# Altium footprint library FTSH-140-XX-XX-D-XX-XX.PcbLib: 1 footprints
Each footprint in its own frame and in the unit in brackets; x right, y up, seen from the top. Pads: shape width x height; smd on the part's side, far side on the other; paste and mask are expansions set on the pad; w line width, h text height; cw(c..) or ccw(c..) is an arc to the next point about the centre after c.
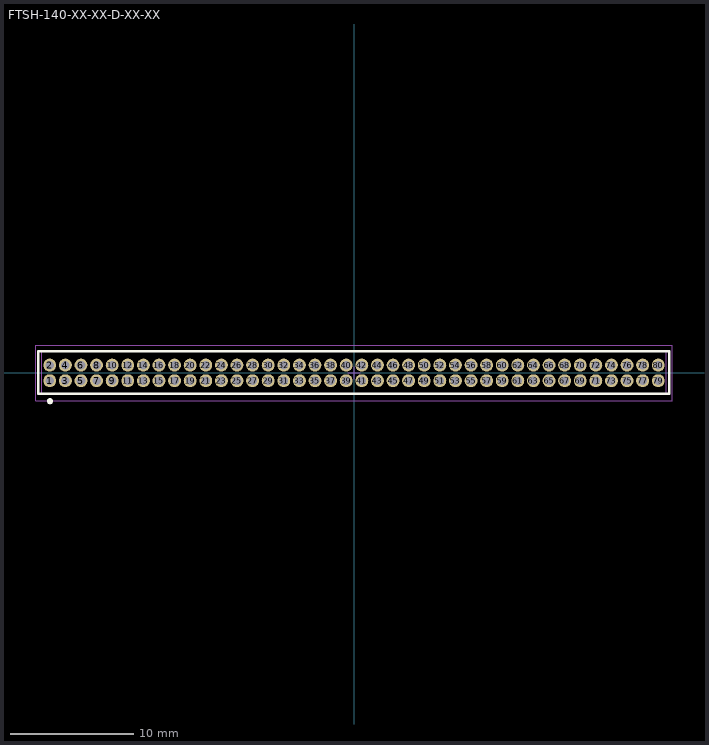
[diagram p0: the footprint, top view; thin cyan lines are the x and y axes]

## FTSH-140-XX-XX-D-XX-XX [mm] "1.27mm pitch, 80 pin, terminal strip; PTH"
height 3.05
pads (80):
  round 1.05 hole 0.7 unplated mask+0: 1(-24.765,-0.635) 2(-24.765,0.635) 3(-23.495,-0.635) 4(-23.495,0.635) 5(-22.225,-0.635) 6(-22.225,0.635) 7(-20.955,-0.635) 8(-20.955,0.635) 9(-19.685,-0.635) 10(-19.685,0.635) 11(-18.415,-0.635) 12(-18.415,0.635) 13(-17.145,-0.635) 14(-17.145,0.635) 15(-15.875,-0.635) 16(-15.875,0.635) 17(-14.605,-0.635) 18(-14.605,0.635) 19(-13.335,-0.635) 20(-13.335,0.635) 21(-12.065,-0.635) 22(-12.065,0.635) 23(-10.795,-0.635) 24(-10.795,0.635) 25(-9.525,-0.635) 26(-9.525,0.635) 27(-8.255,-0.635) 28(-8.255,0.635) 29(-6.985,-0.635) 30(-6.985,0.635) 31(-5.715,-0.635) 32(-5.715,0.635) 33(-4.445,-0.635) 34(-4.445,0.635) 35(-3.175,-0.635) 36(-3.175,0.635) 37(-1.905,-0.635) 38(-1.905,0.635) 39(-0.635,-0.635) 40(-0.635,0.635) 41(0.635,-0.635) 42(0.635,0.635) 43(1.905,-0.635) 44(1.905,0.635) 45(3.175,-0.635) 46(3.175,0.635) 47(4.445,-0.635) 48(4.445,0.635) 49(5.715,-0.635) 50(5.715,0.635) 51(6.985,-0.635) 52(6.985,0.635) 53(8.255,-0.635) 54(8.255,0.635) 55(9.525,-0.635) 56(9.525,0.635) 57(10.795,-0.635) 58(10.795,0.635) 59(12.065,-0.635) 60(12.065,0.635) 61(13.335,-0.635) 62(13.335,0.635) 63(14.605,-0.635) 64(14.605,0.635) 65(15.875,-0.635) 66(15.875,0.635) 67(17.145,-0.635) 68(17.145,0.635) 69(18.415,-0.635) 70(18.415,0.635) 71(19.685,-0.635) 72(19.685,0.635) 73(20.955,-0.635) 74(20.955,0.635) 75(22.225,-0.635) 76(22.225,0.635) 77(23.495,-0.635) 78(23.495,0.635) 79(24.765,-0.635) 80(24.765,0.635)
Top Overlay:
  circle w0.25: c-24.75,-2.3 r0.125
  lines w0.2: -25.7,-1.7 -25.7,1.75 25.65,1.75 25.65,-1.7 -25.7,-1.7
Mechanical 13:
  lines w0.1: -25.4,-1.7 -25.4,1.75 25.4,1.75 25.4,-1.7 -25.4,-1.7
  text ".Designator" at 0.254,0.381 h1.52
Mechanical 15:
  lines w0.05: -0.5,0 0.5,0 ; 0,-0.5 0,0.5 ; -25.9,-2.25 -25.9,2.25 25.9,2.25 25.9,-2.25 -25.9,-2.25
